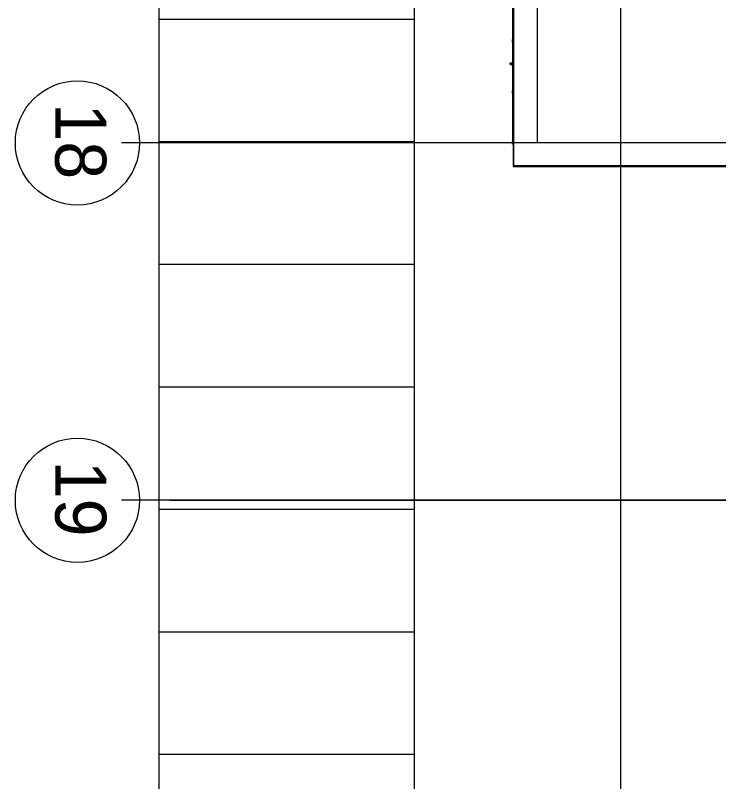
# Model space of a CAD drawing. Extents: x -264165 to -263575, y -1242333 to -1242036.
# Drawn here: x -263923.9 to -263910.13, y -1242208.39 to -1242193.38 of the extents above; entities that cross this region are included whole.
import ezdxf

# ---------------------------------------------------------------- set-up
doc = ezdxf.new("R2010")
doc.units = 0
doc.layers.add('KFA_HESCON_OSI_STAVBY', color=7, linetype='Continuous')
doc.layers.add('KFA_SITUACIA_DRS_VYTYCOVAK_SEDA', color=7, linetype='Continuous')

msp = doc.modelspace()

# ---------------------------------------------------------------- linework, layer by layer
at = {"layer": 'KFA_HESCON_OSI_STAVBY'}
for p, q in [((-263787.486, -1242195.882), (-263921.823, -1242195.882)), ((-263787.486, -1242202.882), (-263921.823, -1242202.882)), ((-263920.885, -1242202.882), (-263905.505, -1242202.882))]:
    msp.add_line(p, q, dxfattribs=at)
for centre in [(-263922.688, -1242195.882), (-263922.688, -1242202.882)]:
    msp.add_circle(centre, 1.216, dxfattribs=at)
at = {"layer": 'KFA_SITUACIA_DRS_VYTYCOVAK_SEDA'}
for p, q in [((-263921.093, -1242087.308), (-263921.093, -1242241.458)), ((-263912.043, -1242228.625), (-263912.043, -1242100.14)), ((-263914.153, -1242132.422), (-263914.153, -1242196.342)), ((-263914.153, -1242132.422), (-263914.153, -1242196.342)), ((-263914.143, -1242196.333), (-263914.143, -1242132.433)), ((-263913.683, -1242132.892), (-263913.683, -1242195.872)), ((-263913.683, -1242132.892), (-263913.683, -1242195.872)), ((-263916.093, -1242187.557), (-263916.093, -1242241.458)), ((-263914.168, -1242192.907), (-263914.168, -1242193.857)), ((-263914.168, -1242192.907), (-263914.168, -1242193.857)), ((-263921.093, -1242193.457), (-263916.093, -1242193.457)), ((-263914.168, -1242193.907), (-263914.168, -1242193.857)), ((-263914.168, -1242193.907), (-263914.168, -1242193.857)), ((-263914.168, -1242193.907), (-263914.168, -1242194.857)), ((-263914.168, -1242193.907), (-263914.168, -1242194.857)), ((-263914.213, -1242194.332), (-263914.21, -1242194.322)), ((-263914.213, -1242194.332), (-263914.21, -1242194.322)), ((-263914.21, -1242194.342), (-263914.213, -1242194.332)), ((-263914.21, -1242194.342), (-263914.213, -1242194.332)), ((-263914.21, -1242194.322), (-263914.203, -1242194.314)), ((-263914.21, -1242194.322), (-263914.203, -1242194.314)), ((-263914.21, -1242194.323), (-263914.21, -1242194.322)), ((-263914.21, -1242194.323), (-263914.21, -1242194.322)), ((-263914.21, -1242194.327), (-263914.21, -1242194.323)), ((-263914.21, -1242194.327), (-263914.21, -1242194.323)), ((-263914.21, -1242194.332), (-263914.21, -1242194.327)), ((-263914.21, -1242194.332), (-263914.21, -1242194.327)), ((-263914.21, -1242194.337), (-263914.21, -1242194.332)), ((-263914.21, -1242194.337), (-263914.21, -1242194.332)), ((-263914.21, -1242194.34), (-263914.21, -1242194.337)), ((-263914.21, -1242194.34), (-263914.21, -1242194.337)), ((-263914.21, -1242194.342), (-263914.21, -1242194.34)), ((-263914.21, -1242194.342), (-263914.21, -1242194.34)), ((-263914.203, -1242194.349), (-263914.21, -1242194.342)), ((-263914.203, -1242194.349), (-263914.21, -1242194.342)), ((-263914.203, -1242194.314), (-263914.193, -1242194.312)), ((-263914.203, -1242194.314), (-263914.193, -1242194.312)), ((-263914.203, -1242194.317), (-263914.203, -1242194.314)), ((-263914.203, -1242194.317), (-263914.203, -1242194.314)), ((-263914.203, -1242194.317), (-263914.193, -1242194.314)), ((-263914.203, -1242194.317), (-263914.193, -1242194.314)), ((-263914.203, -1242194.323), (-263914.203, -1242194.317)), ((-263914.203, -1242194.323), (-263914.203, -1242194.317)), ((-263914.203, -1242194.323), (-263914.193, -1242194.322)), ((-263914.203, -1242194.323), (-263914.193, -1242194.322)), ((-263914.203, -1242194.332), (-263914.203, -1242194.323)), ((-263914.203, -1242194.332), (-263914.203, -1242194.323)), ((-263914.203, -1242194.34), (-263914.203, -1242194.332)), ((-263914.203, -1242194.34), (-263914.203, -1242194.332)), ((-263914.203, -1242194.332), (-263914.193, -1242194.332)), ((-263914.203, -1242194.332), (-263914.193, -1242194.332)), ((-263914.203, -1242194.34), (-263914.193, -1242194.342)), ((-263914.203, -1242194.34), (-263914.193, -1242194.342)), ((-263914.203, -1242194.347), (-263914.203, -1242194.34)), ((-263914.203, -1242194.347), (-263914.203, -1242194.34)), ((-263914.203, -1242194.349), (-263914.203, -1242194.347)), ((-263914.203, -1242194.349), (-263914.203, -1242194.347)), ((-263914.203, -1242194.347), (-263914.193, -1242194.349)), ((-263914.203, -1242194.347), (-263914.193, -1242194.349)), ((-263914.193, -1242194.352), (-263914.203, -1242194.349)), ((-263914.193, -1242194.352), (-263914.203, -1242194.349)), ((-263914.193, -1242194.312), (-263914.183, -1242194.314)), ((-263914.193, -1242194.312), (-263914.183, -1242194.314)), ((-263914.193, -1242194.312), (-263914.193, -1242194.314)), ((-263914.193, -1242194.312), (-263914.193, -1242194.314)), ((-263914.193, -1242194.314), (-263914.183, -1242194.317)), ((-263914.193, -1242194.314), (-263914.183, -1242194.317)), ((-263914.193, -1242194.314), (-263914.193, -1242194.322)), ((-263914.193, -1242194.314), (-263914.193, -1242194.322)), ((-263914.193, -1242194.322), (-263914.193, -1242194.332)), ((-263914.193, -1242194.322), (-263914.193, -1242194.332)), ((-263914.193, -1242194.322), (-263914.183, -1242194.323)), ((-263914.193, -1242194.322), (-263914.183, -1242194.323)), ((-263914.193, -1242194.332), (-263914.193, -1242194.342)), ((-263914.193, -1242194.332), (-263914.193, -1242194.342)), ((-263914.193, -1242194.332), (-263914.183, -1242194.332)), ((-263914.193, -1242194.332), (-263914.183, -1242194.332)), ((-263914.193, -1242194.342), (-263914.183, -1242194.34)), ((-263914.193, -1242194.342), (-263914.183, -1242194.34)), ((-263914.193, -1242194.342), (-263914.193, -1242194.349)), ((-263914.193, -1242194.342), (-263914.193, -1242194.349)), ((-263914.193, -1242194.349), (-263914.183, -1242194.347)), ((-263914.193, -1242194.349), (-263914.183, -1242194.347)), ((-263914.193, -1242194.349), (-263914.193, -1242194.352)), ((-263914.193, -1242194.349), (-263914.193, -1242194.352)), ((-263914.183, -1242194.349), (-263914.193, -1242194.352)), ((-263914.183, -1242194.349), (-263914.193, -1242194.352)), ((-263914.183, -1242194.314), (-263914.176, -1242194.322)), ((-263914.183, -1242194.314), (-263914.176, -1242194.322)), ((-263914.183, -1242194.314), (-263914.183, -1242194.317)), ((-263914.183, -1242194.314), (-263914.183, -1242194.317)), ((-263914.183, -1242194.317), (-263914.183, -1242194.323)), ((-263914.183, -1242194.317), (-263914.183, -1242194.323)), ((-263914.183, -1242194.323), (-263914.183, -1242194.332)), ((-263914.183, -1242194.323), (-263914.183, -1242194.332)), ((-263914.183, -1242194.332), (-263914.183, -1242194.34)), ((-263914.183, -1242194.332), (-263914.183, -1242194.34)), ((-263914.183, -1242194.34), (-263914.183, -1242194.347)), ((-263914.183, -1242194.34), (-263914.183, -1242194.347)), ((-263914.176, -1242194.342), (-263914.183, -1242194.349)), ((-263914.176, -1242194.342), (-263914.183, -1242194.349)), ((-263914.183, -1242194.347), (-263914.183, -1242194.349)), ((-263914.183, -1242194.347), (-263914.183, -1242194.349)), ((-263914.176, -1242194.322), (-263914.168, -1242194.322)), ((-263914.176, -1242194.322), (-263914.168, -1242194.322)), ((-263914.176, -1242194.322), (-263914.176, -1242194.323)), ((-263914.176, -1242194.322), (-263914.176, -1242194.323)), ((-263914.176, -1242194.323), (-263914.168, -1242194.323)), ((-263914.176, -1242194.323), (-263914.168, -1242194.323)), ((-263914.176, -1242194.323), (-263914.176, -1242194.327)), ((-263914.176, -1242194.323), (-263914.176, -1242194.327)), ((-263914.176, -1242194.327), (-263914.168, -1242194.327)), ((-263914.176, -1242194.327), (-263914.168, -1242194.327)), ((-263914.176, -1242194.327), (-263914.176, -1242194.332)), ((-263914.176, -1242194.327), (-263914.176, -1242194.332)), ((-263914.176, -1242194.332), (-263914.168, -1242194.332)), ((-263914.176, -1242194.332), (-263914.168, -1242194.332)), ((-263914.176, -1242194.332), (-263914.176, -1242194.337)), ((-263914.176, -1242194.332), (-263914.176, -1242194.337)), ((-263914.176, -1242194.337), (-263914.168, -1242194.337)), ((-263914.176, -1242194.337), (-263914.168, -1242194.337)), ((-263914.176, -1242194.337), (-263914.176, -1242194.34)), ((-263914.176, -1242194.337), (-263914.176, -1242194.34)), ((-263914.176, -1242194.34), (-263914.168, -1242194.34)), ((-263914.176, -1242194.34), (-263914.168, -1242194.34)), ((-263914.176, -1242194.34), (-263914.176, -1242194.342)), ((-263914.176, -1242194.34), (-263914.176, -1242194.342)), ((-263914.176, -1242194.342), (-263914.168, -1242194.342)), ((-263914.176, -1242194.342), (-263914.168, -1242194.342)), ((-263914.168, -1242194.907), (-263914.168, -1242194.857)), ((-263914.168, -1242194.907), (-263914.168, -1242194.857)), ((-263914.168, -1242194.907), (-263914.168, -1242195.857)), ((-263914.168, -1242194.907), (-263914.168, -1242195.857)), ((-263921.093, -1242195.857), (-263916.093, -1242195.857)), ((-263914.168, -1242195.907), (-263914.168, -1242195.857)), ((-263914.168, -1242195.907), (-263914.168, -1242195.857)), ((-263914.153, -1242195.907), (-263914.168, -1242195.907)), ((-263914.153, -1242195.907), (-263914.168, -1242195.907)), ((-263913.683, -1242195.872), (-263903.828, -1242195.872)), ((-263913.683, -1242195.872), (-263903.828, -1242195.872)), ((-263914.153, -1242196.342), (-263903.358, -1242196.342)), ((-263914.153, -1242196.342), (-263903.358, -1242196.342)), ((-263909.043, -1242196.333), (-263914.143, -1242196.333)), ((-263921.093, -1242198.257), (-263916.093, -1242198.257)), ((-263921.093, -1242200.657), (-263916.093, -1242200.657)), ((-263921.093, -1242203.057), (-263916.093, -1242203.057)), ((-263921.093, -1242205.457), (-263916.093, -1242205.457)), ((-263921.093, -1242207.857), (-263916.093, -1242207.857))]:
    msp.add_line(p, q, dxfattribs=at)

# ---------------------------------------------------------------- texts
at = {"layer": 'KFA_HESCON_OSI_STAVBY'}
for s, p in [('18', (-263923.123, -1242195.105)), ('19', (-263923.123, -1242202.105))]:
    msp.add_text(s, height=1, rotation=270, dxfattribs=at).set_placement(p)

doc.saveas('drawing.dxf')
